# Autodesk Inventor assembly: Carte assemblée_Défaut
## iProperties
Shininess: 64.0
Length Units: 11269
Angle Units: 11279
Time Units: 11290
Mass Units: 11283
Length Display Precision: 3
Angle Display Precision: 2
Compacted: True
Created: 2006-01
Part Number: Carte assemblée_Défaut
Document SubType Name: Assembly
Designer: riri
Density: 0.0
Volumn: 0.0
Area: 0.0
PropertySet Name: Model Information
Control State: 0
Master: False
Checked Out: False
Author: riri
